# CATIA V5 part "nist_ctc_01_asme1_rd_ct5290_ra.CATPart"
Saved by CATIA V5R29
Part number: NIST Test Case 1 CATIA V5R29 RC
Revision: C
Nomenclature: NIST Complex Test Case 1 V5R29
Property "Modeled By": "Rich Eckenrode, RECON Services.com - Revised by DS"
Property "CAGE Code": "64JW1"
Property "Company": "RECON Services Incorporated"
Bounding box of the stored display mesh (mm): x -400 to 400, y -225 to 225, z -100 to 50
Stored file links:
  E:\users\dgn\TPS V5\Import-export annotations\Step\PMI representation 2015\NIST UC\CTC\nist_ctc_01_asme1_ct5210_rd - V5R29.CATPart
  Z:\NIST\300 Models\CATIA V5R21\NIST Test Case 1 CATIA V5R21.CATPart
  E:\users\dgn\TPS V5\Import-export annotations\Step\PMI representation 2015\NIST UC\CTC\nist_ctc_01_asme1_ct5210_rd.CATPart
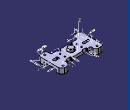
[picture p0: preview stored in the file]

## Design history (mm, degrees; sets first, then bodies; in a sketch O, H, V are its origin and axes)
TTRSSet1
AxisSystem1: origin (-325, -175, 0), X (1, 0, 0), Y (0, 1, 0), Z (0, 0, 1)
f4a2d38f3ddc11d3a929006094b99c4b_11 "CATTPSSet"
Body1 (main body)
  Sketch1 on xy-plane, origin (0, 0, 0), H (1, 0, 0), V (0, 1, 0)
    line L1 (-350, 225) -> (-300, 225)
    line L2 (400, 175) -> (400, -175)
    line L3 (350, -225) -> (300, -225)
    line L4 (-400, -175) -> (-400, 175)
    line L5 (400, 175) -> (350, 225)
    point P1 (400, 175)
    arc A1 centre (350, -175) radius 50 from (400, -175) to (350, -225) cw
    arc A2 centre (-350, -175) radius 50 from (-350, -225) to (-400, -175) cw
    arc A3 centre (-350, 175) radius 50 from (-400, 175) to (-350, 225) cw
    line L6 (-225, -125) -> (-138.8675, -125)
    line L7 (250, -150) -> (250, -175)
    line L8 (-250, -175) -> (-250, -150)
    point P12 (-250, 287.2108)
    line L9 (250, 175) -> (250, 150)
    line L10 (225, 125) -> (192.5, 125)
    line L11 (-250, 150) -> (-250, 175)
    point P13 (250, 125)
    line L12 (-300, -225) -> (-350, -225)
    line L13 (300, 225) -> (350, 225)
    line L14 (245, 25) -> (325, 25)
    line L15 (335, 15) -> (335, -15)
    line L16 (325, -25) -> (245, -25)
    line L17 (235, -15) -> (235, 15)
    point P14 (-345, 20)
    line L18 (-325, 20) -> (-245, 20)
    construction line L19 (-225, 20) -> (-225, -20)
    line L20 (-245, -20) -> (-325, -20)
    construction line L21 (-345, -20) -> (-345, 20)
    point P15 (-225, 20)
    point P16 (-225, -20)
    point P17 (-345, -20)
    arc A4 centre (-325, 0) radius 20 from (-325, 20) to (-325, -20) ccw
    arc A5 centre (-245, 0) radius 20 from (-245, -20) to (-245, 20) ccw
    arc A6 centre (245, 15) radius 10 from (245, 25) to (235, 15) ccw
    arc A7 centre (245, -15) radius 10 from (235, -15) to (245, -25) ccw
    arc A8 centre (325, -15) radius 10 from (325, -25) to (335, -15) ccw
    arc A9 centre (325, 15) radius 10 from (335, 15) to (325, 25) ccw
    point P36 (0, 57.735)
    point P37 (0, -57.7351)
    arc A10 centre (-225, 150) radius 25 from (-250, 150) to (-225, 125) ccw
    arc A11 centre (225, 150) radius 25 from (225, 125) to (250, 150) ccw
    arc A12 centre (-225, -150) radius 25 from (-250, -150) to (-225, -125) cw
    arc A13 centre (225, -150) radius 25 from (225, -125) to (250, -150) cw
    line L22 (-107.5, 125) -> (-107.5, 110)
    line L23 (-117.5, 100) -> (-182.5, 100)
    line L24 (-192.5, 110) -> (-192.5, 125)
    point P50 (107.5, 149.7627)
    line L25 (192.5, 125) -> (192.5, 110)
    line L26 (182.5, 100) -> (117.5, 100)
    line L27 (107.5, 110) -> (107.5, 125)
    line L28 (107.5, 125) -> (-107.5, 125)
    line L29 (-192.5, 125) -> (-225, 125)
    arc A14 centre (-182.5, 110) radius 10 from (-192.5, 110) to (-182.5, 100) ccw
    arc A15 centre (-117.5, 110) radius 10 from (-117.5, 100) to (-107.5, 110) ccw
    arc A16 centre (117.5, 110) radius 10 from (107.5, 110) to (117.5, 100) ccw
    arc A17 centre (182.5, 110) radius 10 from (182.5, 100) to (192.5, 110) ccw
    construction line L30 (-110, -82.8088) -> (-110, -157.0762)
    construction line L31 (110, -82.8088) -> (110, -157.0762)
    axis line L32 (-120.3049, -95) -> (124.2405, -95)
    arc A18 centre (-110, -95) radius 10 from (-101.3397, -90) to (-118.6603, -90) ccw
    point P73 (-110, -95)
    arc A19 centre (110, -95) radius 10 from (118.6603, -90) to (101.3397, -90) ccw
    point P74 (110, -95)
    line L33 (138.8675, -125) -> (118.6603, -90)
    line L34 (81.1325, -125) -> (101.3397, -90)
    line L35 (138.8675, -125) -> (225, -125)
    line L36 (-81.1325, -125) -> (-101.3397, -90)
    line L37 (-138.8675, -125) -> (-118.6603, -90)
    line L38 (-81.1325, -125) -> (81.1325, -125)
    arc A20 centre (300, -175) radius 50 from (250, -175) to (300, -225) ccw
    arc A21 centre (-300, -175) radius 50 from (-250, -175) to (-300, -225) cw
    arc A22 centre (-300, 175) radius 50 from (-300, 225) to (-250, 175) cw
    arc A23 centre (300, 175) radius 50 from (300, 225) to (250, 175) ccw
    distance L4 L2 = 800
    distance L3 L1 = 450
    distance V L4 = 400
    distance H L3 = 225
    angle L2 L5 = 45
    distance L1 P1 = 50
    distance L6 L10 = 250
    distance L12 L6 = 100
    distance L8 L7 = 500
    distance L4 L8 = 150
    radius A2 = 50
    radius A3 = 50
    radius A1 = 50
    distance L14 L16 = 50
    distance L17 L15 = 100
    distance L14 H = 25
    distance V L17 = 235
    distance V L19 = 225
    distance H L18 = 20
    distance L19 L21 = 120
    distance L20 L18 = 40
    radius A6 = 10
    radius A7 = 10
    radius A8 = 10
    radius A9 = 10
    distance P37 V = 0
    distance H P36 = 57.735
    radius A10 = 25
    radius A11 = 25
    radius A12 = 25
    radius A13 = 25
    distance L10 L26 = 25
    distance L10 L23 = 25
    distance L25 L27 = 85
    distance L22 L24 = 85
    distance V L27 = 107.5
    distance V L22 = 107.5
    radius A14 = 10
    radius A15 = 10
    radius A16 = 10
    radius A17 = 10
    distance V L30 = 110
    distance V L31 = 110
    distance L32 L6 = 30
    radius A19 = 10
    radius A18 = 10
    angle L34 L33 = 60
    angle L34 L31 = 30
    angle L37 L36 = 60
    angle L37 L30 = 30
    radius A20 = 50
    radius A21 = 50
    radius A22 = 50
    radius A23 = 50
    horizontal: L1 H, L3 H, L6 H, L10 H, L14 H, L16 H, L18 H, L20 H, L23 H, L26 H, L32 H
    vertical: L2 V, L4 V, L7 V, L8 V, L9 V, L11 V, L15 V, L17 V, L19 V, L21 V, L22 V, L24 V, L25 V, L27 V, L30 V, L31 V
    tangency: A1 L2, A1 L3, A2 L3, A2 L4, A3 L4, A3 L1, A4 L18, A4 L21, A4 L20, A5 L18, A5 L19, A5 L20, A6 L14, A6 L17, A7 L17, A7 L16, A8 L16, A8 L15, A9 L15, A9 L14, A10 L11, A10 L10, A11 L10, A11 L9, A12 L8, A12 L6, A13 L6, A13 L7, A14 L24, A14 L23, A15 L23, A15 L22, A16 L27, A16 L26, A17 L26, A17 L25, L33 A19, L34 A19, L36 A18, L37 A18, A20 L7, A20 L3, A21 L8, A21 L12, A22 L1, A22 L11, A23 L13, A23 L9
    coincidence: P12 L8, P13 L7, L3 L12, L1 L13, P12 L11, P14 L18, P17 L20, P15 L18, P16 L20, L10 P13, L9 P13, L10 L28, L28 L29, P50 L27, P73 L32, P73 L30, P74 L32, P74 L31, L6 L35, L6 L38
  Pad1: profile Sketch1, direction (0, 0, -1), length 100
  Sketch2 on xy-plane, origin (0, 0, 0), H (1, 0, 0), V (0, 1, 0)
    point P1 (0, 57.735)
    line L1 (0, 57.735) -> (-50, 28.8675)
    line L2 (-50, 28.8675) -> (-50, -28.8675)
    line L3 (-50, -28.8675) -> (0, -57.7351)
    point P4 (0, -57.7351)
    line L4 (0, 57.735) -> (50, 28.8675)
    line L5 (50, 28.8675) -> (50, -28.8675)
    line L6 (50, -28.8675) -> (0, -57.7351)
    distance L2 L5 = 100
    distance L1 L6 = 100
    distance L4 L3 = 100
    angle L6 L3 = 120
    angle L3 L2 = 120
    distance L2 V = 50
    distance P4 V = 0
    distance H P1 = 57.735
    vertical: L2 V, L5 V
  Pad2: profile Sketch2, direction (0, 0, 1), length 50
  Sketch3 on end face of Pad1, origin (0, 0, -100), H (1, 0, 0), V (0, -1, 0)
    line L1 (-250, 300) -> (250, 300)
    line L2 (250, 300) -> (250, 125)
    line L3 (250, -300) -> (-250, -300)
    line L4 (-250, -300) -> (-250, -125)
    line L5 (500, 125) -> (250, 125)
    line L6 (-500, 125) -> (-500, -125)
    line L7 (-500, -125) -> (-250, -125)
    line L8 (500, -125) -> (500, 125)
    line L9 (250, -125) -> (500, -125)
    line L10 (-250, 125) -> (-500, 125)
    line L11 (250, -125) -> (250, -300)
    line L12 (-250, 125) -> (-250, 300)
    distance L5 L9 = 250
    distance L2 L12 = 500
    distance V L12 = 250
    distance H L5 = 125
    distance L1 L3 = 600
    distance L6 L8 = 1000
    distance V L6 = 500
    distance H L3 = 300
    horizontal: L1 H, L3 H, L5 H, L7 H
    vertical: L2 V, L4 V, L6 V, L8 V
    coincidence: L7 L9, L5 L10, L2 L11, L4 L12
  Pocket1: profile Sketch3, direction (0, 0, 1), length 50
  Fillet1: radius 10, on edge [face of Pocket1 from Sketch3.L7 | end face of Pocket1]; edge [face of Pocket1 from Sketch3.L9 | end face of Pocket1]; edge [face of Pocket1 from Sketch3.L5 | end face of Pocket1]; edge [face of Pocket1 from Sketch3.L10 | end face of Pocket1]; edge [face of Pocket1 | end face of Pocket1] (x4)
  Sketch4 on face of Pad1 from Sketch1.L38, origin (-24.3901, -125, -27.1952), H (1, 0, 0), V (0, 0, 1)
    point P1 (-5.6099, 2.1952)
    reference intersected line E1 through (0, 27.1952) direction (-1, 0) from xy-plane
    reference intersected line E2 through (24.3901, 0) direction (0, 1) from yz-plane
    distance E1 P1 = 25
    distance E2 P1 = 30
  Hole1: placed by Sketch4, at (-30, -125, -25) direction (0, 1, 0), diameter 20, depth 45, V-bottom angle 118
  RectPattern1: of Hole1, direction 1 instances 2, spacing 60, along edge [end face of Pocket1 | face of Pad1 from Sketch1.L38]
  Sketch5 on start face of Pad1, origin (-326.9152, -179.2519, 0), H (1, 0, 0), V (0, 1, 0)
    point P1 (1.9152, 4.2519)
    reference intersected line E1 through (326.9152, 0) direction (0, 1) from yz-plane
    reference intersected line E2 through (0, 179.2519) direction (-1, 0) from zx-plane
    distance E1 P1 = 325
    distance E2 P1 = 175
  Hole2: placed by Sketch5, at (-325, -175, 0) direction (0, 0, -1), diameter 35, through (limit type 3)
  RectPattern2: of Hole2, direction 1 instances 2, spacing 650, along edge [face of Pad1 from Sketch1.L35 | start face of Pad1], direction 2 instances 2, spacing 350, along edge [face of Pad1 from Sketch1.L2 | start face of Pad1]
  Sketch6 on start face of Pad1, origin (-109.3199, 45.2523, 0), H (1, 0, 0), V (0, 1, 0)
    point P1 (-50.6801, -0.2523)
    reference intersected line E1 through (109.3199, 0) direction (0, 1) from yz-plane
    reference intersected line E2 through (0, -45.2523) direction (-1, 0) from zx-plane
    distance E1 P1 = 160
    distance E2 P1 = 45
  Hole3: placed by Sketch6, at (-160, 45, 0) direction (0, 0, -1), diameter 25, through (limit type 3)
  RectPattern3: of Hole3, direction 1 instances 2, spacing 320, along edge [face of Pad1 from Sketch1.L35 | start face of Pad1], direction 2 instances 2, spacing 90, along edge [face of Pad1 from Sketch1.L2 | start face of Pad1] reversed
  Fillet2: radius 5, on edge [start face of Pad1 | face of Pad2 from Sketch2.L5]; edge [start face of Pad1 | face of Pad2 from Sketch2.L6]; edge [start face of Pad1 | face of Pad2 from Sketch2.L3]; edge [start face of Pad1 | face of Pad2 from Sketch2.L2]; edge [start face of Pad1 | face of Pad2 from Sketch2.L1]; edge [start face of Pad1 | face of Pad2 from Sketch2.L4]
  Chamfer1: length 5, angle 45, on end face of Pad2
  Point1: type Center, Curve edge [start face of Pad1 | face of Hole2]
